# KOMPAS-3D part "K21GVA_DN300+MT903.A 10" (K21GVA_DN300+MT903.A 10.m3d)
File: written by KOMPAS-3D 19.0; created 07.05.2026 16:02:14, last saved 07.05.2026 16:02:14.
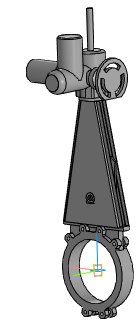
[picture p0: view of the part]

Document properties: Автор: Энергия; Полное имя файла: ..\K21GVA_DN50-DN1000+MT903.A\K21GVA_DN300+MT903.A 10.a3d

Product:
- Part/product: K21GVA_DN300+MT903.A 10
    Масса: 123.095

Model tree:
1. Операция без истории:1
